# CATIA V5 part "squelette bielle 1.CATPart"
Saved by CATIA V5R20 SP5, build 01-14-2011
Part number: squelette bielle 1
Bounding box of the stored display mesh (mm): x -10277.03 to 0, y -10000 to 10000, z 8458.138 to 10472.604
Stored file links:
  M:\EU_thinkMotion\IAO_2010\iao\IAO_MMS_Groupe1\Problemes\gduval\Gduval\train d'aterrissage squelette + piece kinematic\squelette bielle 1.CATPart
  M:\EU_thinkMotion\IAO_2010\iao\IAO_MMS_Groupe1\Problemes\gduval\Gduval\train d'aterrissage squelette + piece kinematic\train d'aterrissage.CATProduct
  M:\EU_thinkMotion\IAO_2010\iao\IAO_MMS_Groupe1\Problemes\gduval\Gduval\train d'aterrissage squelette + piece kinematic\squelette de base.CATPart
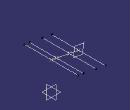
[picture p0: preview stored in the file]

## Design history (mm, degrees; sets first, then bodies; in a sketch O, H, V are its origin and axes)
Set1
  Point1 to Point4: linked copy from another document
  Plane1: linked copy from another document
Body1 (main body)
  Line1: type PtPt, FirstPoint Point1, SecondPoint Point2
  Line2: type PtPt, FirstPoint Point2, SecondPoint Point3
  Line3: type PtPt, FirstPoint Point3, SecondPoint Point4
  Line4: type Normal, RefPoint Point1, RefSkin Plane1, Start 10000, End -10000
  Line5: type Normal, RefPoint Point2, RefSkin Plane1, Start 10000, End -10000
  Line6: type Normal, RefPoint Point3, RefSkin Plane1, Start 10000, End -10000
  Line7: type Normal, RefPoint Point4, RefSkin Plane1, Start 10000, End -10000
  Plane2: type Offset, RefPlane Plane1, Offset 0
